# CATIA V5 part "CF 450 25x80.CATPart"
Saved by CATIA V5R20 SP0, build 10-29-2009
Part number: CF 450 25x80
Definition: NONE
Nomenclature: CF 450 25x80
Source: Unknown
Description: CF 450 25x80
Bounding box of the stored display mesh (mm): x -22 to 22, y 0 to 80, z -22 to 22
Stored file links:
  C:\Users\Utente\Desktop\IO LAVORO\3D X SITO CF\X SITO\CF 450\CF 450 25x80.CATPart
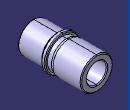
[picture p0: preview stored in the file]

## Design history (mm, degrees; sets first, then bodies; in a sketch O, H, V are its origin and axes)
Body1 "CF 450 25x80" (main body)
  Solid1: solid without history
